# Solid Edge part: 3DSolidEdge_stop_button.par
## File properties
Author: Administrator
Last saved by: Administrator
Revision: 48
Accuracy: 0.990
Agile_Description: Stop Button Part
Modeled_By: L. Conard
Part_Number: ITEM-SE-00007
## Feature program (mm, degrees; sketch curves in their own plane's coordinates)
body "unnamed Body 1"
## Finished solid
Body 1: solid body, 6 faces, 5 edges, 0 vertices.
  Faces by surface: plane 3, cylinder 2, torus 1
  Edges by curve: circle 5
Bounding box of the edges (mm; curved faces can reach further): 10.000 x 10.000 x 3.200, from (-5, -5, 0) to (5, 5, 3.2).
Cylindrical faces by radius (mm): R2.75 x1, R5 x1
Toroidal faces (ring radius, tube radius in mm): R4 r1 x1
Planar faces by outward normal: +z 2, -z 1
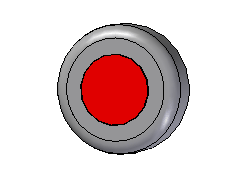
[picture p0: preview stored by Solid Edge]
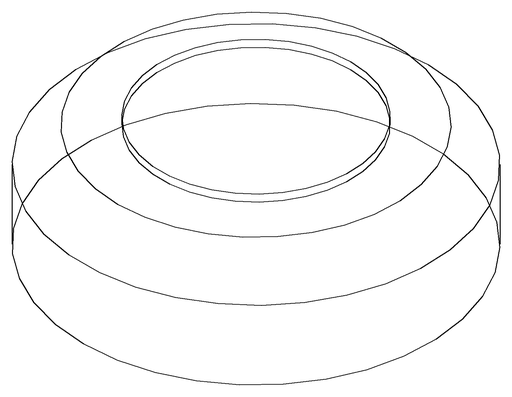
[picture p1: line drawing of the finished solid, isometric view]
